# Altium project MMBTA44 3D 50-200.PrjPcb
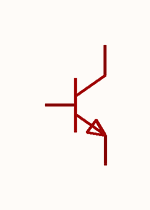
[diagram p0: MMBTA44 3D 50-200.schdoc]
1 sheet, 1 parts. Net scope: global (net labels, ports and power ports of the same name join across sheets).

## Sheet MMBTA44 3D 50-200.schdoc
size 127 x 101 mm

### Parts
Q?  mmbta44(range:50-200)  [SOT-23-3_L2.9-W1.6-P1.90-LS2.8-BR]  (value not drawn)

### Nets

Not connected (* = marked no-connect by the designer): Q? 1(B) 2(E) 3(C)

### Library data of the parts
Q? = mmbta44(range:50-200): 晶体管类型:NPN;集电极电流(Ic):200mA;集射极击穿电压(Vceo):400V;耗散功率(Pd):350mW;直流电流增益(hFE):50;; Manufacturer: CJ(江苏长电/长晶); AddInBom: yes; SymbolName: MMBTA44 3D 50-200; ModelId: 89cb27a44ab2466697082bb9fd73a7d0; ModelName: SOT-23-3L_L2.9-W1.6-H1.1-LS2.8-P0.95; ModelTransform: 114.173,110.236,0,90,0,0,0,0,0; type: NPN; Current - Collector(Ic): 200mA; Collector - Emitter Voltage VCEO: 400V; Pd - Power Dissipation: 350mW; DC Current Gain: 50; Current - Collector Cutoff: 100nA; Vce Saturation(VCE(sat)): 750mV; Emitter-Base Voltage(Vebo): 6V; Number: 1个NPN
